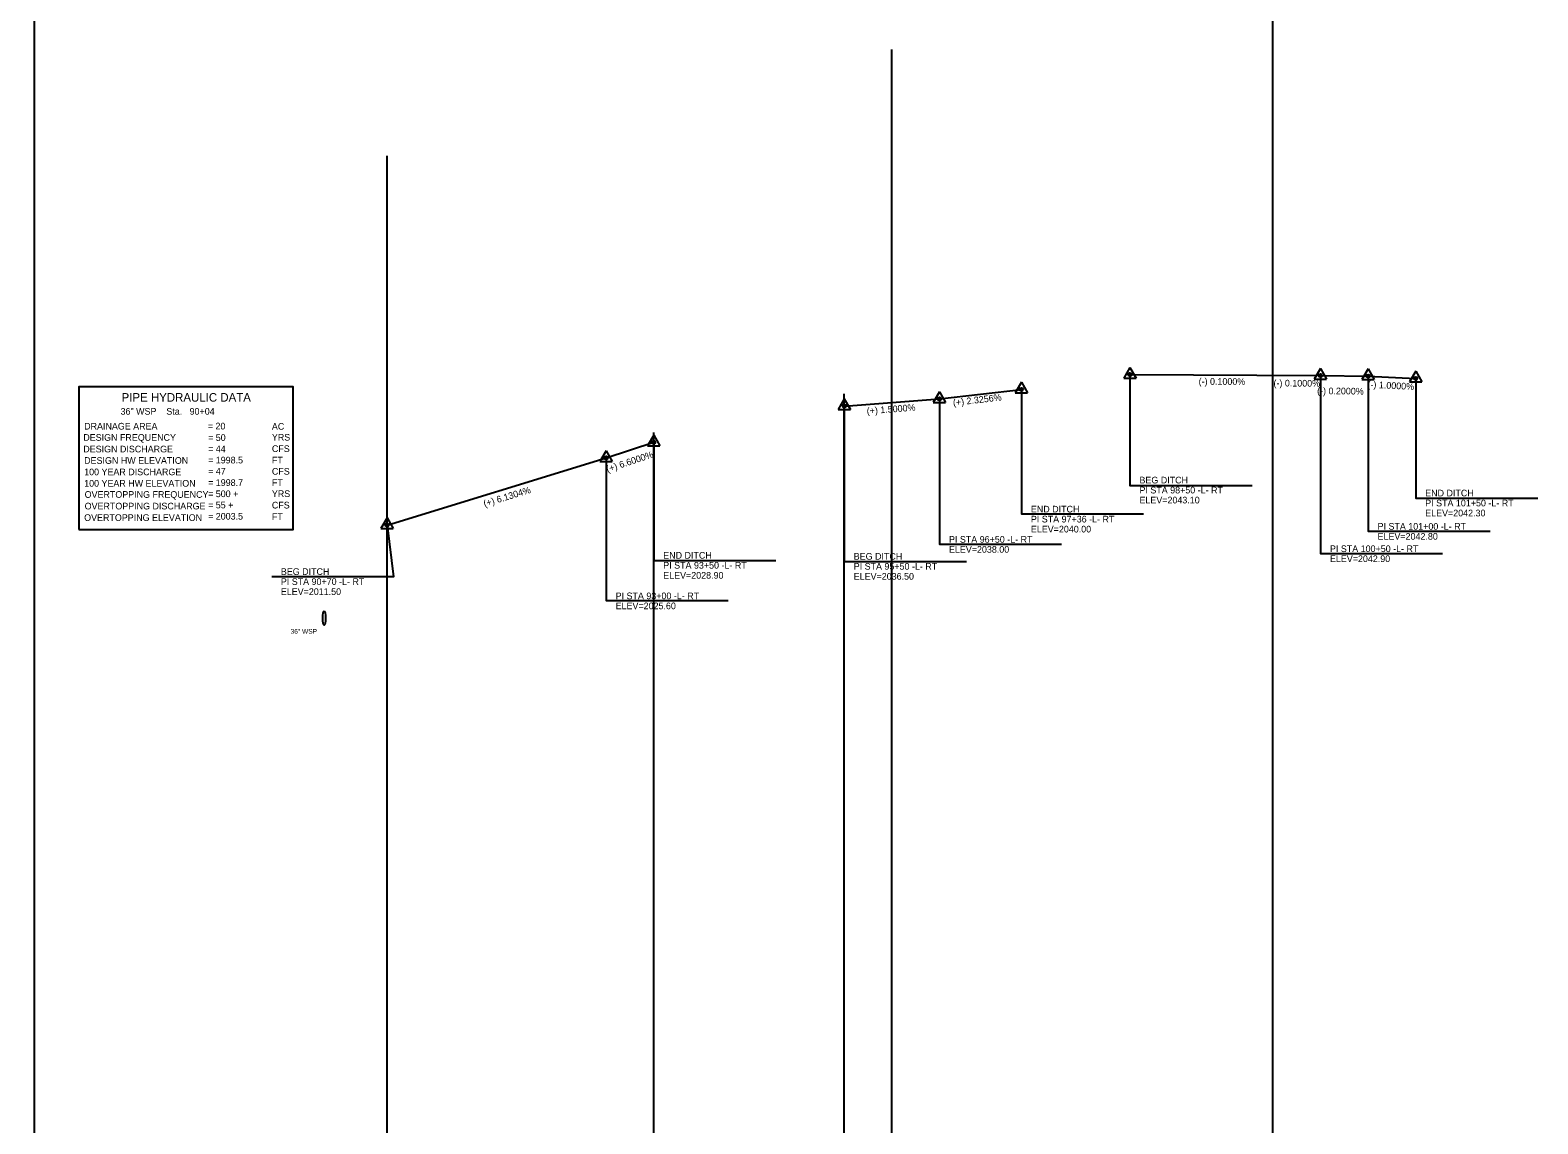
# Model space of a CAD drawing. Extents: x 1025306 to 1036906, y 638983 to 643947.
# Drawn here: x 1033001 to 1034584, y 641918 to 643067 of the extents above; entities that cross this region are included whole.
import ezdxf

# ---------------------------------------------------------------- set-up
doc = ezdxf.new("R2010")
doc.units = 0
for name, color, linetype in [('Default', 7, 'Continuous'), ('Prop PFL Cross Pipe CELL', 7, 'Continuous'), ('Prop PFL Cross Pipe Text CELL', 7, 'Continuous'), ('Prop PFL Pipe Hydraulic Data CELL', 7, 'Continuous'), ('Prop Vertical Profile Ditch Grade Right', 7, 'Continuous'), ('Prop Vertical Profile Ditch Grade Right Label', 7, 'Continuous'), ('Prop VPI Ditch Grade Right Label', 7, 'Continuous'), ('Scratch_Level_0', 7, 'Continuous'), ('Scratch_Level_3', 7, 'Continuous')]:
    doc.layers.add(name, color=color, linetype=linetype)

msp = doc.modelspace()

# ---------------------------------------------------------------- linework, layer by layer
at = {"layer": 'Default'}
for p, q in [((1034155.6, 642712.4), (1034149.1, 642701.2)), ((1034149.1, 642701.2), (1034162.1, 642701.2)), ((1034155.6, 642712.4), (1034162.1, 642701.2)), ((1034355.6, 642711.4), (1034349.1, 642700.2)), ((1034349.1, 642700.2), (1034362.1, 642700.2)), ((1034355.6, 642711.4), (1034362.1, 642700.2)), ((1034405.6, 642710.9), (1034399.1, 642699.7)), ((1034399.1, 642699.7), (1034412.1, 642699.7)), ((1034405.6, 642710.9), (1034412.1, 642699.7)), ((1034455.6, 642708.4), (1034449.1, 642697.2)), ((1034455.6, 642708.4), (1034462.1, 642697.2)), ((1033955.6, 642686.9), (1033949.1, 642675.7)), ((1033955.6, 642686.9), (1033962.1, 642675.7)), ((1034041.6, 642696.9), (1034035.1, 642685.7)), ((1034035.1, 642685.7), (1034048.1, 642685.7)), ((1034041.6, 642696.9), (1034048.1, 642685.7)), ((1034449.1, 642697.2), (1034462.1, 642697.2)), ((1033855.6, 642679.4), (1033849.1, 642668.2)), ((1033849.1, 642668.2), (1033862.1, 642668.2)), ((1033855.6, 642679.4), (1033862.1, 642668.2)), ((1033949.1, 642675.7), (1033962.1, 642675.7)), ((1033655.6, 642641.4), (1033649.1, 642630.2)), ((1033655.6, 642641.4), (1033662.1, 642630.2)), ((1033605.6, 642624.9), (1033599.1, 642613.7)), ((1033605.6, 642624.9), (1033612.1, 642613.7)), ((1033649.1, 642630.2), (1033662.1, 642630.2)), ((1033599.1, 642613.7), (1033612.1, 642613.7)), ((1033375.6, 642554.4), (1033369.1, 642543.2)), ((1033369.1, 642543.2), (1033382.1, 642543.2)), ((1033375.6, 642554.4), (1033382.1, 642543.2))]:
    msp.add_line(p, q, dxfattribs=at)
for centre, radius in [((1034155.6, 642704.9), 1.75), ((1034155.6, 642704.9), 1.2), ((1034355.6, 642703.9), 1.75), ((1034355.6, 642703.9), 1.2), ((1034405.6, 642703.4), 1.75), ((1034405.6, 642703.4), 1.2), ((1034455.6, 642700.9), 1.75), ((1034455.6, 642700.9), 1.2), ((1034041.6, 642689.4), 1.75), ((1034041.6, 642689.4), 1.2), ((1033855.6, 642671.9), 1.75), ((1033855.6, 642671.9), 1.2), ((1033955.6, 642679.4), 1.75), ((1033955.6, 642679.4), 1.2), ((1033655.6, 642633.9), 1.75), ((1033655.6, 642633.9), 1.2), ((1033605.6, 642617.4), 1.75), ((1033605.6, 642617.4), 1.2), ((1033375.6, 642546.9), 1.75), ((1033375.6, 642546.9), 1.2)]:
    msp.add_circle(centre, radius, dxfattribs=at)
at = {"layer": 'Prop PFL Cross Pipe CELL'}
msp.add_ellipse((1033309.6, 642449.2), major_axis=(0, 7.5), ratio=0.2, dxfattribs=at)
at = {"layer": 'Prop PFL Pipe Hydraulic Data CELL'}
msp.add_lwpolyline([(1033052.1, 642542.1), (1033277.1, 642542.1), (1033277.1, 642692.1), (1033052.1, 642692.1)], close=True, dxfattribs=at)
at = {"layer": 'Prop Vertical Profile Ditch Grade Right'}
for points in [[(1034155.6, 642704.9), (1034355.6, 642703.9), (1034405.6, 642703.4), (1034455.6, 642700.9)], [(1033855.6, 642671.9), (1033955.6, 642679.4), (1034041.6, 642689.4)], [(1033375.6, 642546.9), (1033605.6, 642617.4), (1033655.6, 642633.9)]]:
    msp.add_lwpolyline(points, dxfattribs=at)
at = {"layer": 'Prop VPI Ditch Grade Right Label'}
for points in [[(1034155.6, 642704.9), (1034155.6, 642588.6), (1034283.9, 642588.6)], [(1034355.6, 642703.9), (1034355.6, 642517), (1034483.9, 642517)], [(1034405.6, 642703.4), (1034405.6, 642540.5), (1034533.9, 642540.5)], [(1034455.6, 642700.9), (1034455.6, 642575.3), (1034583.9, 642575.3)], [(1034041.6, 642689.4), (1034041.6, 642558.5), (1034169.9, 642558.5)], [(1033855.6, 642671.9), (1033855.6, 642508.5), (1033983.9, 642508.5)], [(1033955.6, 642679.4), (1033955.6, 642526.8), (1034083.9, 642526.8)], [(1033655.6, 642633.9), (1033655.6, 642509.6), (1033783.9, 642509.6)], [(1033605.6, 642617.4), (1033605.6, 642467.5), (1033733.9, 642467.5)], [(1033375.6, 642546.9), (1033382.4, 642492.5), (1033254.5, 642492.5)]]:
    msp.add_lwpolyline(points, dxfattribs=at)
for centre in [(1034155.6, 642704.9), (1034355.6, 642703.9), (1034405.6, 642703.4), (1034455.6, 642700.9), (1034041.6, 642689.4), (1033855.6, 642671.9), (1033955.6, 642679.4), (1033655.6, 642633.9), (1033655.6, 642633.9), (1033605.6, 642617.4), (1033375.6, 642546.9), (1033375.6, 642546.9)]:
    msp.add_circle(centre, 0.5, dxfattribs=at)
at = {"layer": 'Scratch_Level_0'}
msp.add_line((1033655.6, 642633.9), (1033655.6, 642644), dxfattribs=at)
for points in [[(1025305.6, 639889.4), (1033905.6, 639889.4), (1033905.6, 643046.4)], [(1025305.6, 639889.4), (1033375.6, 639889.4), (1033375.6, 642934.5)], [(1025305.6, 639889.4), (1033855.6, 639889.4), (1033855.6, 642684.6)], [(1025305.6, 639889.4), (1033655.6, 639889.4), (1033655.6, 642644)]]:
    msp.add_lwpolyline(points, dxfattribs=at)
at = {"layer": 'Scratch_Level_3'}
for p, q in [((1034305.6, 639889.4), (1034305.6, 643946.5)), ((1033005.6, 639889.4), (1033005.6, 643536.5))]:
    msp.add_line(p, q, dxfattribs=at)

# ---------------------------------------------------------------- texts
at = {"layer": 'Prop PFL Cross Pipe Text CELL'}
msp.add_text('36" WSP', height=5, dxfattribs=at).set_placement((1033274.3, 642432.7))
at = {"layer": 'Prop PFL Pipe Hydraulic Data CELL'}
for s, height, p in [('PIPE HYDRAULIC DATA', 9, (1033096.9, 642676.5)), ('  36" WSP    Sta.   90+04  ', 7, (1033090.6, 642662.8)), ('DRAINAGE AREA', 7, (1033057.6, 642647.2)), ('= 20  ', 7, (1033187.4, 642647.3)), ('AC', 7, (1033254.7, 642647)), ('DESIGN FREQUENCY', 7, (1033056.7, 642635.4)), ('= 50 ', 7, (1033187.7, 642635.2)), ('YRS', 7, (1033254.7, 642635.6)), ('DESIGN DISCHARGE', 7, (1033056.7, 642623.2)), ('= 44 ', 7, (1033187.7, 642623.4)), ('CFS', 7, (1033254.7, 642623.6)), ('DESIGN HW ELEVATION', 7, (1033057.6, 642611.2)), ('100 YEAR DISCHARGE', 7, (1033057.6, 642599.2)), ('= 1998.5', 7, (1033187.7, 642611.6)), ('= 47 ', 7, (1033187.7, 642599.8)), ('CFS', 7, (1033254.7, 642599.8)), ('FT', 7, (1033254.7, 642611.6)), ('100 YEAR HW ELEVATION', 7, (1033057.6, 642587.2)), ('= 1998.7', 7, (1033187.7, 642588)), ('FT', 7, (1033254.7, 642588)), ('OVERTOPPING FREQUENCY', 7, (1033058.1, 642575.5)), ('= 500 +  ', 7, (1033187.7, 642576.2)), ('YRS', 7, (1033254.7, 642576.3)), ('OVERTOPPING ELEVATION', 7, (1033057.6, 642551.2)), ('OVERTOPPING DISCHARGE', 7, (1033058.1, 642563.3)), ('= 55 +  ', 7, (1033187.7, 642564.4)), ('= 2003.5', 7, (1033187.7, 642552.6)), ('CFS', 7, (1033254.7, 642564.3)), ('FT', 7, (1033254.7, 642552.2))]:
    msp.add_text(s, height=height, dxfattribs=at).set_placement(p)
at = {"layer": 'Prop Vertical Profile Ditch Grade Right Label'}
for s, rotation, p in [('(-) 0.1000%', 359.7135, (1034227.7, 642694.3)), ('(-) 0.1000%', 359.7135, (1034306.3, 642692.5)), ('(+) 2.3256%', 6.6325, (1033970.2, 642671.9)), ('(-) 0.2000%', 359.4271, (1034352.1, 642684.4)), ('(-) 1.0000%', 357.1376, (1034404.9, 642691.2)), ('(+) 1.5000%', 4.2892, (1033879.5, 642663.2)), ('(+) 6.6000%', 18.2629, (1033607.1, 642602.1)), ('(+) 6.1304%', 17.0414, (1033478.1, 642565.8))]:
    msp.add_text(s, height=7, rotation=rotation, dxfattribs=at).set_placement(p)
at = {"layer": 'Prop VPI Ditch Grade Right Label'}
for s, p in [('BEG DITCH', (1034165.6, 642590.6)), ('PI STA 98+50 -L- RT', (1034165.6, 642580.1)), ('ELEV=2043.10', (1034165.6, 642569.6)), ('END DITCH', (1034465.6, 642577)), ('PI STA 101+50 -L- RT', (1034465.6, 642566.5)), ('END DITCH', (1034051.6, 642560.1)), ('ELEV=2042.30', (1034465.6, 642556)), ('PI STA 97+36 -L- RT', (1034051.6, 642549.6)), ('ELEV=2040.00', (1034051.6, 642539.1)), ('PI STA 101+00 -L- RT', (1034415.6, 642542)), ('PI STA 96+50 -L- RT', (1033965.6, 642528.3)), ('PI STA 100+50 -L- RT', (1034365.6, 642518.5)), ('ELEV=2042.80', (1034415.6, 642531.5)), ('END DITCH', (1033665.6, 642511.6)), ('BEG DITCH', (1033865.6, 642510.5)), ('ELEV=2038.00', (1033965.6, 642517.8)), ('ELEV=2042.90', (1034365.6, 642508)), ('BEG DITCH', (1033264.1, 642494.5)), ('PI STA 93+50 -L- RT', (1033665.6, 642501.1)), ('ELEV=2028.90', (1033665.6, 642490.6)), ('PI STA 95+50 -L- RT', (1033865.6, 642500)), ('ELEV=2036.50', (1033865.6, 642489.5)), ('PI STA 90+70 -L- RT', (1033264.1, 642484)), ('ELEV=2011.50', (1033264.1, 642473.5)), ('PI STA 93+00 -L- RT', (1033615.6, 642469)), ('ELEV=2025.60', (1033615.6, 642458.5))]:
    msp.add_text(s, height=7, dxfattribs=at).set_placement(p)

doc.saveas('drawing.dxf')
